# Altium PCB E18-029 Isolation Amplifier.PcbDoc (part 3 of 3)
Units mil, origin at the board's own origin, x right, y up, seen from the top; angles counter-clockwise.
Board outline 5740 x 5970 mil, 4 copper layers (Component Side, V+, V-, Ground), stack 33.234 mil thick; 359 components, 170 nets, 952 pads, 232 vias.
Unrouted connection lines stored in the file: 60.
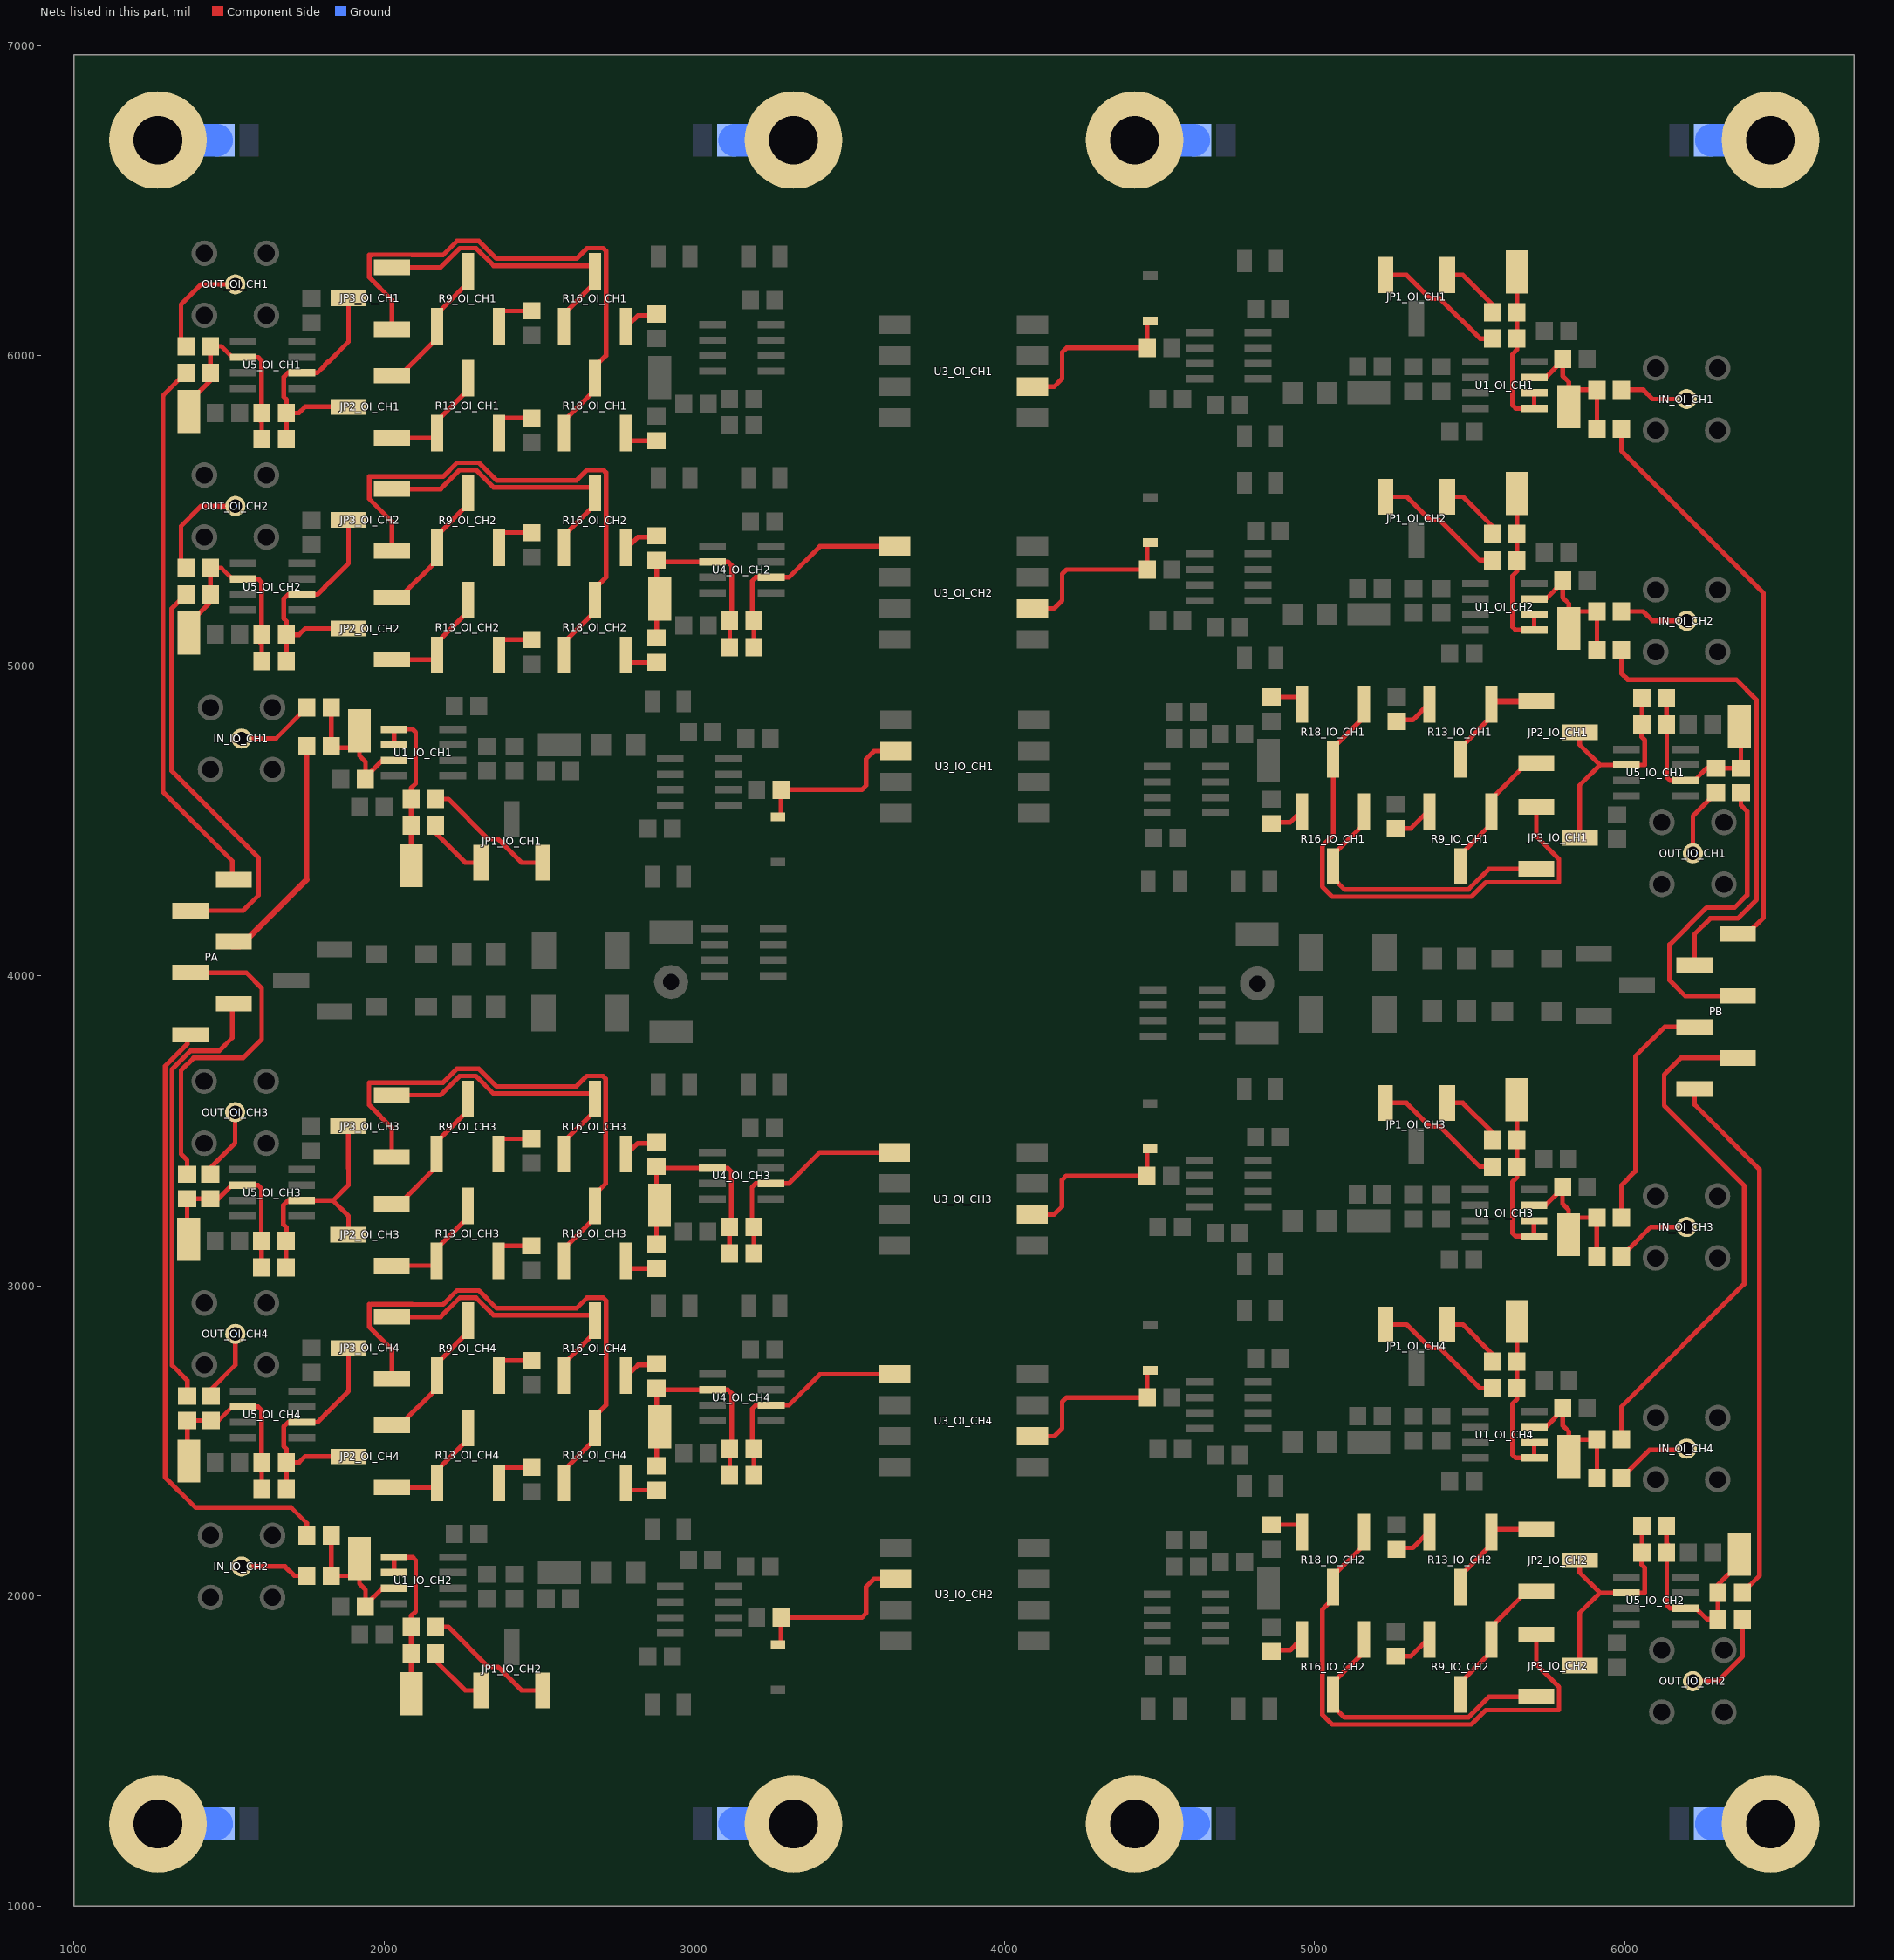
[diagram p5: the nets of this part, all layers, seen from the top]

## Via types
v1: diameter 50, hole 28, Component Side to Ground, tented both sides, 226 vias
v2: diameter 100, hole 50, Component Side to Ground, tented both sides, 6 vias

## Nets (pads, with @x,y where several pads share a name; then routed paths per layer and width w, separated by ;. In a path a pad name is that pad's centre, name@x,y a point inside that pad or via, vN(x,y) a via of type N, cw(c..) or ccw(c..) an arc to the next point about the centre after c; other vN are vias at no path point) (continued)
NetC3_OI_CH2_1: C3_OI_CH2.1 R10_OI_CH2.2 R14_OI_CH2.2 R17_OI_CH2.2 TP4_OI_CH2.1 U4_OI_CH2.6 | length 819.3
  Component Side w15: R17_OI_CH2.2@2878.46,5089.37 2878.46,5205 TP4_OI_CH2.1@2888.46,5215 2878.46,5225 R14_OI_CH2.2@2878.46,5340.63 ; R14_OI_CH2.2@2878.46,5340 2883.46,5335 3103.98,5335 ; U4_OI_CH2.6@3058.98,5335 3108.46,5335 3120.28,5323.18 3120.28,5151.19 R10_OI_CH2.2@3114.09,5145 ; R10_OI_CH2.2@3113.46,5145 3114.09,5144.37 C3_OI_CH2.1@3114.09,5060
NetC3_OI_CH2_2: C3_OI_CH2.2 R10_OI_CH2.1 U3_OI_CH2.5 U4_OI_CH2.2 | length 724.1
  Component Side w15: C3_OI_CH2.2@3192.83,5060 3192.83,5144.37 R10_OI_CH2.1@3193.46,5145 ; R10_OI_CH2.1@3192.83,5145 3186.64,5151.19 3186.64,5273.18 3198.46,5285 U4_OI_CH2.2@3247.95,5285 3305,5285 3405,5385 U3_OI_CH2.5@3646.46,5385 U3_OI_CH2.5@3648.46,5385
NetC3_OI_CH3_1: C3_OI_CH3.1 R10_OI_CH3.2 R14_OI_CH3.2 R17_OI_CH3.2 TP4_OI_CH3.1 U4_OI_CH3.6 | length 819.3
  Component Side w15: R17_OI_CH3.2@2877.83,3134.37 2877.83,3250 TP4_OI_CH3.1@2887.83,3260 2877.83,3270 R14_OI_CH3.2@2877.83,3385.63 ; R14_OI_CH3.2@2877.83,3385 2882.83,3380 3103.35,3380 ; U4_OI_CH3.6@3058.35,3380 3107.83,3380 3119.65,3368.18 3119.65,3196.19 R10_OI_CH3.2@3113.46,3190 ; R10_OI_CH3.2@3112.83,3190 3113.46,3189.37 C3_OI_CH3.1@3113.46,3105
NetC3_OI_CH3_2: C3_OI_CH3.2 R10_OI_CH3.1 U3_OI_CH3.5 U4_OI_CH3.2 | length 724.1
  Component Side w15: C3_OI_CH3.2@3192.2,3105 3192.2,3189.37 R10_OI_CH3.1@3192.83,3190 ; R10_OI_CH3.1@3192.2,3190 3186.01,3196.19 3186.01,3318.18 3197.83,3330 U4_OI_CH3.2@3247.32,3330 3304.37,3330 3404.37,3430 U3_OI_CH3.5@3645.83,3430 U3_OI_CH3.5@3647.83,3430
NetC3_OI_CH4_1: C3_OI_CH4.1 R10_OI_CH4.2 R14_OI_CH4.2 R17_OI_CH4.2 TP4_OI_CH4.1 U4_OI_CH4.6 | length 819.3
  Component Side w15: R17_OI_CH4.2@2878.46,2419.37 2878.46,2535 TP4_OI_CH4.1@2888.46,2545 2878.46,2555 R14_OI_CH4.2@2878.46,2670.63 ; R14_OI_CH4.2@2878.46,2670 2883.46,2665 3103.98,2665 ; U4_OI_CH4.6@3058.98,2665 3108.46,2665 3120.28,2653.18 3120.28,2481.19 R10_OI_CH4.2@3114.09,2475 ; R10_OI_CH4.2@3113.46,2475 3114.09,2474.37 C3_OI_CH4.1@3114.09,2390
NetC3_OI_CH4_2: C3_OI_CH4.2 R10_OI_CH4.1 U3_OI_CH4.5 U4_OI_CH4.2 | length 724.1
  Component Side w15: C3_OI_CH4.2@3192.83,2390 3192.83,2474.37 R10_OI_CH4.1@3193.46,2475 ; R10_OI_CH4.1@3192.83,2475 3186.64,2481.19 3186.64,2603.18 3198.46,2615 U4_OI_CH4.2@3247.95,2615 3305,2615 3405,2715 U3_OI_CH4.5@3646.46,2715 U3_OI_CH4.5@3648.46,2715
NetC4_IO_CH1_1: C4_IO_CH1.1 R12_IO_CH1.1 R15_IO_CH1.2 R21_IO_CH1.2 TP5_IO_CH1.1 U5_IO_CH1.6 | length 679.3
  Component Side w15: C4_IO_CH1.1@6135,4895 6135,4840 R12_IO_CH1.1@6150,4825 ; R12_IO_CH1.1@6135.68,4810 6135.68,4640.68 6146.36,4630 U5_IO_CH1.6@6225,4630 ; U5_IO_CH1.6@6194.49,4630 U5_IO_CH1.6@6225,4630 ; U5_IO_CH1.6@6230,4630 U5_IO_CH1.6@6225,4630 ; R21_IO_CH1.2@6295,4669.37 6374.37,4669.37 R15_IO_CH1.2@6375,4670 ; R21_IO_CH1.2@6295,4670 6265,4670 U5_IO_CH1.6@6225,4630 ; TP5_IO_CH1.1@6370,4805 6375,4800 R15_IO_CH1.2@6375,4670 ; R15_IO_CH1.2@6375,4669.37 R15_IO_CH1.2@6375,4670
NetC4_IO_CH1_2: C4_IO_CH1.2 JP2_IO_CH1.2 JP3_IO_CH1.2 R12_IO_CH1.2 U5_IO_CH1.2 | length 764.3
  Component Side w15: JP3_IO_CH1.2@5855,4445 5855,4615 5920,4680 ; JP2_IO_CH1.2@5855,4785 5855,4745 5920,4680 ; U5_IO_CH1.2@6005.51,4680 6065,4680 6065,4760 6055,4770 R12_IO_CH1.2@6055,4810 ; U5_IO_CH1.2@6010,4680 5920,4680 ; R12_IO_CH1.2@6055.63,4810 6055.63,4890.63 C4_IO_CH1.2@6060,4895
NetC4_IO_CH2_1: C4_IO_CH2.1 R12_IO_CH2.1 R15_IO_CH2.2 R21_IO_CH2.2 TP5_IO_CH2.1 U5_IO_CH2.6 | length 638.7
  Component Side w15: C4_IO_CH2.1@6135,2225 6135,2170 R12_IO_CH2.1@6150,2155 ; R12_IO_CH2.1@6135.68,2140 6135.68,1970.68 6146.36,1960 6230,1960 6265,1925 6300,1925 R21_IO_CH2.2@6300.63,1925.63 ; R15_IO_CH2.2@6300,2010 6300.63,2009.37 R21_IO_CH2.2@6300.63,1925.63 ; R21_IO_CH2.2@6300.63,1925 R21_IO_CH2.2@6300.63,1925.63 ; R15_IO_CH2.2@6300.63,2010 6300.63,2035.63 TP5_IO_CH2.1@6370,2105
NetC4_IO_CH2_2: C4_IO_CH2.2 JP2_IO_CH2.2 JP3_IO_CH2.2 R12_IO_CH2.2 U5_IO_CH2.2 | length 764.3
  Component Side w15: JP3_IO_CH2.2@5855,1775 5855,1945 5920,2010 ; JP2_IO_CH2.2@5855,2115 5855,2075 5920,2010 ; U5_IO_CH2.2@6005.51,2010 6065,2010 6065,2090 6055,2100 R12_IO_CH2.2@6055,2140 ; U5_IO_CH2.2@6010,2010 5920,2010 ; R12_IO_CH2.2@6055.63,2140 6055.63,2220.63 C4_IO_CH2.2@6060,2225
NetC4_OI_CH1_1: C4_OI_CH1.1 R12_OI_CH1.1 R15_OI_CH1.2 R21_OI_CH1.2 TP5_OI_CH1.1 U5_OI_CH1.6 | length 638.7
  Component Side w15: TP5_OI_CH1.1@1370,5850 1439.37,5919.37 R15_OI_CH1.2@1439.37,5945 ; R21_OI_CH1.2@1439.37,6030 R21_OI_CH1.2@1439.37,6029.37 ; R15_OI_CH1.2@1440,5945 1439.37,5945.63 R21_OI_CH1.2@1439.37,6029.37 ; R12_OI_CH1.1@1590,5800 1605,5785 C4_OI_CH1.1@1605,5730 ; R12_OI_CH1.1@1604.32,5815 1604.32,5984.32 1593.64,5995 1510,5995 1475,6030 1440,6030 R21_OI_CH1.2@1439.37,6029.37
NetC4_OI_CH1_2: C4_OI_CH1.2 JP2_OI_CH1.2 JP3_OI_CH1.2 R12_OI_CH1.2 U5_OI_CH1.2 | length 814.3
  Component Side w15: C4_OI_CH1.2@1684.37,5730 R12_OI_CH1.2@1684.37,5815 1684.37,5819.37 R12_OI_CH1.2@1685,5820 ; U5_OI_CH1.2@1734.49,5945 1690,5945 1675.68,5930.68 1675.68,5867.69 1685,5858.37 R12_OI_CH1.2@1685,5820 ; U5_OI_CH1.2@1735,5945 1785,5945 1809.96,5969.96 1809.96,5971.42 1819.04,5980.5 ; 1820,5980 1885,6045 JP3_OI_CH1.2@1885,6185 ; JP2_OI_CH1.2@1885,5835 1745,5835 1725,5815 1685,5815 R12_OI_CH1.2@1685,5820
NetC4_OI_CH2_1: C4_OI_CH2.1 R12_OI_CH2.1 R15_OI_CH2.2 R21_OI_CH2.2 TP5_OI_CH2.1 U5_OI_CH2.6 | length 638.7
  Component Side w15: TP5_OI_CH2.1@1370,5135 1439.37,5204.37 R15_OI_CH2.2@1439.37,5230 ; R21_OI_CH2.2@1439.37,5315 R21_OI_CH2.2@1439.37,5314.37 ; R15_OI_CH2.2@1440,5230 1439.37,5230.63 R21_OI_CH2.2@1439.37,5314.37 ; R12_OI_CH2.1@1590,5085 1605,5070 C4_OI_CH2.1@1605,5015 ; R12_OI_CH2.1@1604.32,5100 1604.32,5269.32 1593.64,5280 1510,5280 1475,5315 1440,5315 R21_OI_CH2.2@1439.37,5314.37
NetC4_OI_CH2_2: C4_OI_CH2.2 JP2_OI_CH2.2 JP3_OI_CH2.2 R12_OI_CH2.2 U5_OI_CH2.2 | length 814.3
  Component Side w15: C4_OI_CH2.2@1684.37,5015 R12_OI_CH2.2@1684.37,5100 1684.37,5104.37 R12_OI_CH2.2@1685,5105 ; U5_OI_CH2.2@1734.49,5230 1690,5230 1675.68,5215.68 1675.68,5152.69 1685,5143.37 R12_OI_CH2.2@1685,5105 ; U5_OI_CH2.2@1735,5230 1785,5230 1809.96,5254.96 1809.96,5256.42 1819.04,5265.5 ; 1820,5265 1885,5330 JP3_OI_CH2.2@1885,5470 ; JP2_OI_CH2.2@1885,5120 1745,5120 1725,5100 1685,5100 R12_OI_CH2.2@1685,5105
NetC4_OI_CH3_1: C4_OI_CH3.1 R12_OI_CH3.1 R15_OI_CH3.2 R21_OI_CH3.2 TP5_OI_CH3.1 U5_OI_CH3.6 | length 681.4
  Component Side w15: R15_OI_CH3.2@1364.37,3280.63 R15_OI_CH3.2@1364.37,3280 ; TP5_OI_CH3.1@1369.37,3145 1364.37,3150 R15_OI_CH3.2@1364.37,3280 ; R21_OI_CH3.2@1439.37,3280 1464.37,3280 U5_OI_CH3.6@1509.37,3325 ; R21_OI_CH3.2@1439.37,3280.63 1365,3280.63 R15_OI_CH3.2@1364.37,3280 ; U5_OI_CH3.6@1544.88,3325 U5_OI_CH3.6@1509.37,3325 ; R12_OI_CH3.1@1589.37,3130 1604.37,3115 C4_OI_CH3.1@1604.37,3060 ; R12_OI_CH3.1@1603.69,3145 1603.69,3314.32 1593.01,3325 U5_OI_CH3.6@1509.37,3325
NetC4_OI_CH3_2: C4_OI_CH3.2 JP2_OI_CH3.2 JP3_OI_CH3.2 R12_OI_CH3.2 U5_OI_CH3.2 | length 769.3
  Component Side w15: C4_OI_CH3.2@1683.74,3060 R12_OI_CH3.2@1683.74,3145 1683.74,3149.37 R12_OI_CH3.2@1684.37,3150 ; R12_OI_CH3.2@1684.37,3145 R12_OI_CH3.2@1684.37,3150 ; U5_OI_CH3.2@1733.86,3275 1689.37,3275 1675.05,3260.68 1675.05,3197.69 1684.37,3188.37 R12_OI_CH3.2@1684.37,3150 ; U5_OI_CH3.2@1734.37,3275 1835,3275 ; 1884.37,3379.37 JP3_OI_CH3.2@1884.37,3515 ; 1885,3380 1885,3325 1835,3275 ; JP2_OI_CH3.2@1890,3165 1885,3170 1885,3225 1835,3275
NetC4_OI_CH4_1: C4_OI_CH4.1 R12_OI_CH4.1 R15_OI_CH4.2 R21_OI_CH4.2 TP5_OI_CH4.1 U5_OI_CH4.6 | length 681.4
  Component Side w15: R15_OI_CH4.2@1365,2565.63 R15_OI_CH4.2@1365,2565 ; TP5_OI_CH4.1@1370,2430 1365,2435 R15_OI_CH4.2@1365,2565 ; R21_OI_CH4.2@1440,2565 1465,2565 U5_OI_CH4.6@1510,2610 ; R21_OI_CH4.2@1440,2565.63 1365.63,2565.63 R15_OI_CH4.2@1365,2565 ; U5_OI_CH4.6@1545.51,2610 U5_OI_CH4.6@1510,2610 ; R12_OI_CH4.1@1590,2415 1605,2400 C4_OI_CH4.1@1605,2345 ; R12_OI_CH4.1@1604.32,2430 1604.32,2599.32 1593.64,2610 U5_OI_CH4.6@1510,2610
NetC4_OI_CH4_2: C4_OI_CH4.2 JP2_OI_CH4.2 JP3_OI_CH4.2 R12_OI_CH4.2 U5_OI_CH4.2 | length 814.3
  Component Side w15: C4_OI_CH4.2@1684.37,2345 R12_OI_CH4.2@1684.37,2430 1684.37,2434.37 R12_OI_CH4.2@1685,2435 ; U5_OI_CH4.2@1734.49,2560 1690,2560 1675.68,2545.68 1675.68,2482.69 1685,2473.37 R12_OI_CH4.2@1685,2435 ; U5_OI_CH4.2@1735,2560 1785,2560 1809.96,2584.96 1809.96,2586.42 1819.04,2595.5 ; 1820,2595 1885,2660 JP3_OI_CH4.2@1885,2800 ; JP2_OI_CH4.2@1885,2450 1745,2450 1725,2430 1685,2430 R12_OI_CH4.2@1685,2435
NetD1_IO_CH1_2: D1_IO_CH1.2 R5_IO_CH1.2 U3_IO_CH1.2 | length 591.9
  Component Side w15: R5_IO_CH1.2@3265,4600 R5_IO_CH1.2@3279.37,4614.37 ; R5_IO_CH1.2@3275,4600 R5_IO_CH1.2@3279.37,4600 ; D1_IO_CH1.2@3279.37,4524.37 R5_IO_CH1.2@3279.37,4600 ; U3_IO_CH1.2@3630,4725 U3_IO_CH1.2@3649.54,4725 3579.53,4725 3553.87,4699.34 3553.87,4613.87 3540,4600 R5_IO_CH1.2@3279.37,4600
NetD1_IO_CH2_2: D1_IO_CH2.2 R5_IO_CH2.2 U3_IO_CH2.2 | length 591.9
  Component Side w15: R5_IO_CH2.2@3265,1930 R5_IO_CH2.2@3279.37,1944.37 ; R5_IO_CH2.2@3275,1930 R5_IO_CH2.2@3279.37,1930 ; D1_IO_CH2.2@3279.37,1854.37 R5_IO_CH2.2@3279.37,1930 ; U3_IO_CH2.2@3630,2055 U3_IO_CH2.2@3649.54,2055 3579.53,2055 3553.87,2029.34 3553.87,1943.87 3540,1930 R5_IO_CH2.2@3279.37,1930
NetD1_OI_CH1_2: D1_OI_CH1.2 R5_OI_CH1.2 U3_OI_CH1.2 | length 572.3
  Component Side w15: U3_OI_CH1.2@4090.46,5900 4160.47,5900 4186.13,5925.66 4186.13,6011.13 4200,6025 R5_OI_CH1.2@4460.63,6025 ; R5_OI_CH1.2@4460.63,6010.63 R5_OI_CH1.2@4475,6025 ; D1_OI_CH1.2@4460.63,6100.63 R5_OI_CH1.2@4460.63,6025 ; R5_OI_CH1.2@4465,6025 R5_OI_CH1.2@4460.63,6025
NetD1_OI_CH2_2: D1_OI_CH2.2 R5_OI_CH2.2 U3_OI_CH2.2 | length 572.3
  Component Side w15: U3_OI_CH2.2@4090.46,5185 4160.47,5185 4186.13,5210.66 4186.13,5296.13 4200,5310 R5_OI_CH2.2@4460.63,5310 ; R5_OI_CH2.2@4460.63,5295.63 R5_OI_CH2.2@4475,5310 ; D1_OI_CH2.2@4460.63,5385.63 R5_OI_CH2.2@4460.63,5310 ; R5_OI_CH2.2@4465,5310 R5_OI_CH2.2@4460.63,5310
NetD1_OI_CH3_2: D1_OI_CH3.2 R5_OI_CH3.2 U3_OI_CH3.2 | length 572.3
  Component Side w15: U3_OI_CH3.2@4089.83,3230 4159.84,3230 4185.5,3255.66 4185.5,3341.13 4199.37,3355 R5_OI_CH3.2@4460,3355 ; R5_OI_CH3.2@4460,3340.63 R5_OI_CH3.2@4474.37,3355 ; D1_OI_CH3.2@4460,3430.63 R5_OI_CH3.2@4460,3355 ; R5_OI_CH3.2@4464.37,3355 R5_OI_CH3.2@4460,3355
NetD1_OI_CH4_2: D1_OI_CH4.2 R5_OI_CH4.2 U3_OI_CH4.2 | length 572.3
  Component Side w15: U3_OI_CH4.2@4090.46,2515 4160.47,2515 4186.13,2540.66 4186.13,2626.13 4200,2640 R5_OI_CH4.2@4460.63,2640 ; R5_OI_CH4.2@4460.63,2625.63 R5_OI_CH4.2@4475,2640 ; D1_OI_CH4.2@4460.63,2715.63 R5_OI_CH4.2@4460.63,2640 ; R5_OI_CH4.2@4465,2640 R5_OI_CH4.2@4460.63,2640
NetIN_IO_CH1_1: IN_IO_CH1.1 R20_IO_CH1.2 | length 252.1
  Component Side w15: IN_IO_CH1.1@1540,4765 1650.63,4765 R20_IO_CH1.2@1750.63,4865
NetIN_IO_CH2_1: IN_IO_CH2.1 R20_IO_CH2.2 | length 223.1
  Component Side w15: IN_IO_CH2.1@1540,2095 1680,2095 1710,2065 R20_IO_CH2.2@1750.63,2065
NetIN_OI_CH1_1: IN_OI_CH1.1 R20_OI_CH1.2 | length 223.1
  Component Side w15: R20_OI_CH1.2@5989.37,5890 6060,5890 6090,5860 IN_OI_CH1.1@6200,5860
NetIN_OI_CH2_1: IN_OI_CH2.1 R20_OI_CH2.2 | length 223.1
  Component Side w15: R20_OI_CH2.2@5989.37,5175 6060,5175 6090,5145 IN_OI_CH2.1@6200,5145
NetIN_OI_CH3_1: IN_OI_CH3.1 R20_OI_CH3.2 | length 250
  Component Side w15: R20_OI_CH3.2@5989.37,3095 6084.37,3190 IN_OI_CH3.1@6199.37,3190 IN_OI_CH3.1@6200,3190
NetIN_OI_CH4_1: IN_OI_CH4.1 R20_OI_CH4.2 | length 250
  Component Side w15: R20_OI_CH4.2@5989.37,2380 6080,2470.63 6195.63,2470.63 IN_OI_CH4.1@6200,2475
NetJP1_IO_CH1_1: JP1_IO_CH1.1 R3_IO_CH1.1 | length 429.9
  Component Side w15: R3_IO_CH1.1@2166.54,4570 2206.54,4570 2335.54,4441 2367.08,4441 2443.08,4365 JP1_IO_CH1.1@2511.54,4365
NetJP1_IO_CH1_3: JP1_IO_CH1.3 R6_IO_CH1.1 | length 209.4
  Component Side w15: R6_IO_CH1.1@2166.54,4485 2166.54,4460 2261.54,4365 JP1_IO_CH1.3@2311.54,4365
NetJP1_IO_CH2_1: JP1_IO_CH2.1 R3_IO_CH2.1 | length 429.9
  Component Side w15: R3_IO_CH2.1@2166.54,1900 2206.54,1900 2335.54,1771 2367.08,1771 2443.08,1695 JP1_IO_CH2.1@2511.54,1695
NetJP1_IO_CH2_3: JP1_IO_CH2.3 R6_IO_CH2.1 | length 209.4
  Component Side w15: R6_IO_CH2.1@2166.54,1815 2166.54,1790 2261.54,1695 JP1_IO_CH2.3@2311.54,1695
NetJP1_OI_CH1_1: JP1_OI_CH1.1 R3_OI_CH1.1 | length 429.9
  Component Side w15: JP1_OI_CH1.1@5228.46,6260 5296.92,6260 5372.92,6184 5404.46,6184 5533.46,6055 R3_OI_CH1.1@5573.46,6055
NetJP1_OI_CH1_3: JP1_OI_CH1.3 R6_OI_CH1.1 | length 209.4
  Component Side w15: JP1_OI_CH1.3@5428.46,6260 5478.46,6260 5573.46,6165 R6_OI_CH1.1@5573.46,6140
NetJP1_OI_CH2_1: JP1_OI_CH2.1 R3_OI_CH2.1 | length 429.9
  Component Side w15: JP1_OI_CH2.1@5228.46,5545 5296.92,5545 5372.92,5469 5404.46,5469 5533.46,5340 R3_OI_CH2.1@5573.46,5340
NetJP1_OI_CH2_3: JP1_OI_CH2.3 R6_OI_CH2.1 | length 209.4
  Component Side w15: JP1_OI_CH2.3@5428.46,5545 5478.46,5545 5573.46,5450 R6_OI_CH2.1@5573.46,5425
NetJP1_OI_CH3_1: JP1_OI_CH3.1 R3_OI_CH3.1 | length 429.9
  Component Side w15: JP1_OI_CH3.1@5227.83,3590 5296.29,3590 5372.29,3514 5403.83,3514 5532.83,3385 R3_OI_CH3.1@5572.83,3385
NetJP1_OI_CH3_3: JP1_OI_CH3.3 R6_OI_CH3.1 | length 209.4
  Component Side w15: JP1_OI_CH3.3@5427.83,3590 5477.83,3590 5572.83,3495 R6_OI_CH3.1@5572.83,3470
NetJP1_OI_CH4_1: JP1_OI_CH4.1 R3_OI_CH4.1 | length 429.9
  Component Side w15: JP1_OI_CH4.1@5228.46,2875 5296.92,2875 5372.92,2799 5404.46,2799 5533.46,2670 R3_OI_CH4.1@5573.46,2670
NetJP1_OI_CH4_3: JP1_OI_CH4.3 R6_OI_CH4.1 | length 209.4
  Component Side w15: JP1_OI_CH4.3@5428.46,2875 5478.46,2875 5573.46,2780 R6_OI_CH4.1@5573.46,2755
NetJP2_IO_CH1_1: JP2_IO_CH1.1 R9_IO_CH1.1 R9_IO_CH1.2 | length 378.3
  Component Side w15: R9_IO_CH1.2@5470,4352.83 5470,4390 R9_IO_CH1.1@5575,4495 ; R9_IO_CH1.1@5570,4570 5685,4685 JP2_IO_CH1.1@5715,4685
NetJP2_IO_CH1_3: JP2_IO_CH1.3 R13_IO_CH1.1 R13_IO_CH1.2 | length 332.7
  Component Side w15: R13_IO_CH1.2@5470,4697.83 5470,4735 R13_IO_CH1.1@5575,4840
  Component Side w20: R13_IO_CH1.1@5570,4880 5575,4885 JP2_IO_CH1.3@5715,4885
NetJP2_IO_CH2_1: JP2_IO_CH2.1 R9_IO_CH2.1 R9_IO_CH2.2 | length 378.3
  Component Side w15: R9_IO_CH2.2@5470,1682.83 5470,1720 R9_IO_CH2.1@5575,1825 ; R9_IO_CH2.1@5570,1900 5685,2015 JP2_IO_CH2.1@5715,2015
NetJP2_IO_CH2_3: JP2_IO_CH2.3 R13_IO_CH2.1 R13_IO_CH2.2 | length 332.7
  Component Side w15: R13_IO_CH2.2@5470,2027.83 5470,2065 R13_IO_CH2.1@5575,2170 ; R13_IO_CH2.1@5570,2210 5575,2215 JP2_IO_CH2.3@5715,2215
NetJP2_OI_CH1_1: JP2_OI_CH1.1 R9_OI_CH1.1 R9_OI_CH1.2 | length 383.2
  Component Side w15: JP2_OI_CH1.1@2025,5935 2050,5935 R9_OI_CH1.1@2170,6055 ; R9_OI_CH1.1@2170,6095 2170,6135 R9_OI_CH1.2@2275,6240
NetJP2_OI_CH1_3: JP2_OI_CH1.3 R13_OI_CH1.1 R13_OI_CH1.2 | length 326.4
  Component Side w15: JP2_OI_CH1.3@2025,5735 R13_OI_CH1.1@2170,5735 ; R13_OI_CH1.1@2170,5750 2170,5790 R13_OI_CH1.2@2270,5890
NetJP2_OI_CH2_1: JP2_OI_CH2.1 R9_OI_CH2.1 R9_OI_CH2.2 | length 383.2
  Component Side w15: JP2_OI_CH2.1@2025,5220 2050,5220 R9_OI_CH2.1@2170,5340 ; R9_OI_CH2.1@2170,5380 2170,5420 R9_OI_CH2.2@2275,5525
NetJP2_OI_CH2_3: JP2_OI_CH2.3 R13_OI_CH2.1 R13_OI_CH2.2 | length 326.4
  Component Side w15: JP2_OI_CH2.3@2025,5020 R13_OI_CH2.1@2170,5020 ; R13_OI_CH2.1@2170,5035 2170,5075 R13_OI_CH2.2@2270,5175
NetJP2_OI_CH3_1: JP2_OI_CH3.1 R9_OI_CH3.1 R9_OI_CH3.2 | length 383.2
  Component Side w15: JP2_OI_CH3.1@2024.37,3265 2049.37,3265 R9_OI_CH3.1@2169.37,3385 ; R9_OI_CH3.1@2169.37,3425 2169.37,3465 R9_OI_CH3.2@2274.37,3570
NetJP2_OI_CH3_3: JP2_OI_CH3.3 R13_OI_CH3.1 R13_OI_CH3.2 | length 326.4
  Component Side w15: JP2_OI_CH3.3@2024.37,3065 R13_OI_CH3.1@2169.37,3065 ; R13_OI_CH3.1@2169.37,3080 2169.37,3120 R13_OI_CH3.2@2269.37,3220
NetJP2_OI_CH4_1: JP2_OI_CH4.1 R9_OI_CH4.1 R9_OI_CH4.2 | length 383.2
  Component Side w15: JP2_OI_CH4.1@2025,2550 2050,2550 R9_OI_CH4.1@2170,2670 ; R9_OI_CH4.1@2170,2710 2170,2750 R9_OI_CH4.2@2275,2855
NetJP2_OI_CH4_3: JP2_OI_CH4.3 R13_OI_CH4.1 R13_OI_CH4.2 | length 326.4
  Component Side w15: JP2_OI_CH4.3@2025,2350 R13_OI_CH4.1@2170,2350 ; R13_OI_CH4.1@2170,2365 2170,2405 R13_OI_CH4.2@2270,2505
NetJP3_IO_CH1_1: JP3_IO_CH1.1 R16_IO_CH1.1 R16_IO_CH1.2 | length 883.5
  Component Side w15: R16_IO_CH1.2@5060,4315 5096.72,4278.28 5496.11,4278.28 5562.83,4345 JP3_IO_CH1.1@5715,4345 ; R16_IO_CH1.2@5060,4352.83 5060,4390 R16_IO_CH1.1@5165,4495
NetJP3_IO_CH1_3: JP3_IO_CH1.3 R18_IO_CH1.1 R18_IO_CH1.2 | length 1586.6
  Component Side w15: R18_IO_CH1.2@5060,4655 5060,4453.5 5024.81,4418.31 5024.81,4287.36 5056.89,4255.28 5505.63,4255.28 5551.85,4301.5 5788.5,4301.5 5788.5,4376.42 5715,4449.92 JP3_IO_CH1.3@5715,4545 ; R18_IO_CH1.2@5060,4735 R18_IO_CH1.1@5155,4830
NetJP3_IO_CH2_1: JP3_IO_CH2.1 R16_IO_CH2.1 R16_IO_CH2.2 | length 883.5
  Component Side w15: R16_IO_CH2.2@5060,1645 5096.72,1608.28 5496.11,1608.28 5562.83,1675 JP3_IO_CH2.1@5715,1675 ; R16_IO_CH2.2@5060,1682.83 5060,1720 R16_IO_CH2.1@5165,1825
NetJP3_IO_CH2_3: JP3_IO_CH2.3 R18_IO_CH2.1 R18_IO_CH2.2 | length 1628.8
  Component Side w15: R18_IO_CH2.2@5060,1990 5024.81,1954.81 5024.81,1617.36 5056.89,1585.28 5505.63,1585.28 5551.85,1631.5 5788.5,1631.5 5788.5,1706.42 5715,1779.92 JP3_IO_CH2.3@5715,1875 ; R18_IO_CH2.2@5060,2027.83 5060,2065 R18_IO_CH2.1@5155,2160
NetJP3_OI_CH1_1: JP3_OI_CH1.1 R16_OI_CH1.1 R16_OI_CH1.2 | length 896.8
  Component Side w15: JP3_OI_CH1.1@2025,6285 2182.17,6285 2243.89,6346.72 2296.11,6346.72 2352.83,6290 2670,6290 2685,6305 R16_OI_CH1.2@2685,6295 ; R16_OI_CH1.1@2585,6140 2680,6235 R16_OI_CH1.2@2680,6272.17
NetJP3_OI_CH1_3: JP3_OI_CH1.3 R18_OI_CH1.1 R18_OI_CH1.2 | length 1660.8
  Component Side w15: JP3_OI_CH1.3@2025,6085 2025,6180.08 1951.5,6253.58 1951.5,6325.5 1952,6325 1960.08,6325 1960.58,6325.5 2089.42,6325.5 2089.92,6325 2189.65,6325 2234.37,6369.72 2305.63,6369.72 2362.35,6313 2620.17,6313 2653.89,6346.72 2706.11,6346.72 2715.19,6337.64 2715.19,6000.19 R18_OI_CH1.2@2680,5965 ; R18_OI_CH1.1@2580,5790 2680,5890 R18_OI_CH1.2@2680,5927.17
NetJP3_OI_CH2_1: JP3_OI_CH2.1 R16_OI_CH2.1 R16_OI_CH2.2 | length 896.8
  Component Side w15: JP3_OI_CH2.1@2025,5570 2182.17,5570 2243.89,5631.72 2296.11,5631.72 2352.83,5575 2670,5575 2685,5590 R16_OI_CH2.2@2685,5580 ; R16_OI_CH2.1@2585,5425 2680,5520 R16_OI_CH2.2@2680,5557.17
NetJP3_OI_CH2_3: JP3_OI_CH2.3 R18_OI_CH2.1 R18_OI_CH2.2 | length 1660.8
  Component Side w15: JP3_OI_CH2.3@2025,5370 2025,5465.08 1951.5,5538.58 1951.5,5610.5 1952,5610 1960.08,5610 1960.58,5610.5 2089.42,5610.5 2089.92,5610 2189.65,5610 2234.37,5654.72 2305.63,5654.72 2362.35,5598 2620.17,5598 2653.89,5631.72 2706.11,5631.72 2715.19,5622.64 2715.19,5285.19 R18_OI_CH2.2@2680,5250 ; R18_OI_CH2.1@2580,5075 2680,5175 R18_OI_CH2.2@2680,5212.17
NetJP3_OI_CH3_1: JP3_OI_CH3.1 R16_OI_CH3.1 R16_OI_CH3.2 | length 896.8
  Component Side w15: JP3_OI_CH3.1@2024.37,3615 2181.54,3615 2243.26,3676.72 2295.48,3676.72 2352.2,3620 2669.37,3620 2684.37,3635 R16_OI_CH3.2@2684.37,3625 ; R16_OI_CH3.1@2584.37,3470 2679.37,3565 R16_OI_CH3.2@2679.37,3602.17
NetJP3_OI_CH3_3: JP3_OI_CH3.3 R18_OI_CH3.1 R18_OI_CH3.2 | length 1660.8
  Component Side w15: JP3_OI_CH3.3@2024.37,3415 2024.37,3510.08 1950.87,3583.58 1950.87,3655.5 1951.37,3655 1959.45,3655 1959.95,3655.5 2088.79,3655.5 2089.29,3655 2189.02,3655 2233.74,3699.72 2305,3699.72 2361.72,3643 2619.54,3643 2653.26,3676.72 2705.48,3676.72 2714.56,3667.64 2714.56,3330.19 R18_OI_CH3.2@2679.37,3295 ; R18_OI_CH3.1@2579.37,3120 2679.37,3220 R18_OI_CH3.2@2679.37,3257.17
NetJP3_OI_CH4_1: JP3_OI_CH4.1 R16_OI_CH4.1 R16_OI_CH4.2 | length 896.8
  Component Side w15: JP3_OI_CH4.1@2025,2900 2182.17,2900 2243.89,2961.72 2296.11,2961.72 2352.83,2905 2670,2905 2685,2920 R16_OI_CH4.2@2685,2910 ; R16_OI_CH4.1@2585,2755 2680,2850 R16_OI_CH4.2@2680,2887.17
NetJP3_OI_CH4_3: JP3_OI_CH4.3 R18_OI_CH4.1 R18_OI_CH4.2 | length 1660.8
  Component Side w15: JP3_OI_CH4.3@2025,2700 2025,2795.08 1951.5,2868.58 1951.5,2940.5 1952,2940 1960.08,2940 1960.58,2940.5 2089.42,2940.5 2089.92,2940 2189.65,2940 2234.37,2984.72 2305.63,2984.72 2362.35,2928 2620.17,2928 2653.89,2961.72 2706.11,2961.72 2715.19,2952.64 2715.19,2615.19 R18_OI_CH4.2@2680,2580 ; R18_OI_CH4.1@2580,2405 2680,2505 R18_OI_CH4.2@2680,2542.17
NetJPA1_1: JPA1.1 MA1.1 | length 190
  Ground w105: MA1.1@1270,6695 JPA1.1@1460,6695
NetJPA2_1: JPA2.1 MA2.1 | length 195
  Ground w105: JPA2.1@3130,6695 MA2.1@3320,6695 MA2.1@3325,6695
NetJPA3_1: JPA3.1 MA3.1 | length 195
  Ground w105: MA3.1@1265,1265 MA3.1@1270,1265 JPA3.1@1460,1265
NetJPA4_1: JPA4.1 MA4.1 | length 190
  Ground w105: JPA4.1@3130,1265 MA4.1@3320,1265
NetJPB1_1: JPB1.1 MB1.1 | length 195
  Ground w105: MB1.1@4415,6695 MB1.1@4420,6695 JPB1.1@4610,6695
NetJPB2_1: JPB2.1 MB2.1 | length 190
  Ground w105: JPB2.1@6280,6695 MB2.1@6470,6695
NetJPB3_1: JPB3.1 MB3.1 | length 190
  Ground w105: MB3.1@4420,1265 JPB3.1@4610,1265
NetJPB4_1: JPB4.1 MB4.1 | length 190
  Ground w105: JPB4.1@6280,1265 MB4.1@6470,1265
NetOUT_IO_CH1_1: OUT_IO_CH1.1 R21_IO_CH1.1 | length 226.7
  Component Side w15: OUT_IO_CH1.1@6220,4395 6220,4515 6295,4590 R21_IO_CH1.1@6295,4590.63
NetOUT_IO_CH2_1: OUT_IO_CH2.1 R21_IO_CH2.1 | length 313.6
  Component Side w15: OUT_IO_CH2.1@6220,1725 6300.38,1725 6380,1804.62 6380,1924.37 R21_IO_CH2.1@6379.37,1925
NetOUT_OI_CH1_1: OUT_OI_CH1.1 R21_OI_CH1.1 | length 343.4
  Component Side w15: R21_OI_CH1.1@1360.63,6030 1345,6045.63 1345,6165 1410,6230 OUT_OI_CH1.1@1520,6230
NetOUT_OI_CH2_1: OUT_OI_CH2.1 R21_OI_CH2.1 | length 343.4
  Component Side w15: R21_OI_CH2.1@1360.63,5315 1345,5330.63 1345,5450 1410,5515 OUT_OI_CH2.1@1520,5515
NetOUT_OI_CH3_1: OUT_OI_CH3.1 R21_OI_CH3.1 | length 233.8
  Component Side w15: R21_OI_CH3.1@1439.37,3359.37 1439.37,3380 1519.37,3460 OUT_OI_CH3.1@1519.37,3560
NetOUT_OI_CH4_1: OUT_OI_CH4.1 R21_OI_CH4.1 | length 233.8
  Component Side w15: R21_OI_CH4.1@1440,2644.37 1440,2665 1520,2745 OUT_OI_CH4.1@1520,2845
NetR3_IO_CH1_2: R3_IO_CH1.2 R6_IO_CH1.2 TP2_IO_CH1.1 U1_IO_CH1.1 U1_IO_CH1.2 | length 570.1
  Component Side w15: U1_IO_CH1.2@2031.54,4745 2032.05,4745.51 U1_IO_CH1.1@2032.05,4795 2091.54,4795 2101.54,4785 2101.54,4620 2086.54,4605 R3_IO_CH1.2@2086.54,4570 ; TP2_IO_CH1.1@2085,4355 2087.17,4357.17 R6_IO_CH1.2@2087.17,4485 ; R6_IO_CH1.2@2086.54,4485 2087.17,4485.63 R3_IO_CH1.2@2087.17,4570 ; R3_IO_CH1.2@2093.36,4570 2091.54,4570 R3_IO_CH1.2@2096.54,4565
NetR3_IO_CH2_2: R3_IO_CH2.2 R6_IO_CH2.2 TP2_IO_CH2.1 U1_IO_CH2.1 U1_IO_CH2.2 | length 570.1
  Component Side w15: U1_IO_CH2.2@2031.54,2075 2032.05,2075.51 U1_IO_CH2.1@2032.05,2125 2091.54,2125 2101.54,2115 2101.54,1950 2086.54,1935 R3_IO_CH2.2@2086.54,1900 ; TP2_IO_CH2.1@2085,1685 2087.17,1687.17 R6_IO_CH2.2@2087.17,1815 ; R6_IO_CH2.2@2086.54,1815 2087.17,1815.63 R3_IO_CH2.2@2087.17,1900 ; R3_IO_CH2.2@2093.36,1900 2091.54,1900 R3_IO_CH2.2@2096.54,1895
NetR3_OI_CH1_2: R3_OI_CH1.2 R6_OI_CH1.2 TP2_OI_CH1.1 U1_OI_CH1.1 U1_OI_CH1.2 | length 570.1
  Component Side w15: R3_OI_CH1.2@5643.46,6060 5648.46,6055 R3_OI_CH1.2@5646.64,6055 ; R3_OI_CH1.2@5652.83,6055 5652.83,6139.37 R6_OI_CH1.2@5653.46,6140 ; R6_OI_CH1.2@5652.83,6140 5652.83,6267.83 TP2_OI_CH1.1@5655,6270 ; R3_OI_CH1.2@5653.46,6055 5653.46,6020 5638.46,6005 5638.46,5840 5648.46,5830 U1_OI_CH1.1@5707.95,5830 5707.95,5879.49 U1_OI_CH1.2@5708.46,5880
NetR3_OI_CH2_2: R3_OI_CH2.2 R6_OI_CH2.2 TP2_OI_CH2.1 U1_OI_CH2.1 U1_OI_CH2.2 | length 570.1
  Component Side w15: R3_OI_CH2.2@5643.46,5345 5648.46,5340 R3_OI_CH2.2@5646.64,5340 ; R3_OI_CH2.2@5652.83,5340 5652.83,5424.37 R6_OI_CH2.2@5653.46,5425 ; R6_OI_CH2.2@5652.83,5425 5652.83,5552.83 TP2_OI_CH2.1@5655,5555 ; R3_OI_CH2.2@5653.46,5340 5653.46,5305 5638.46,5290 5638.46,5125 5648.46,5115 U1_OI_CH2.1@5707.95,5115 5707.95,5164.49 U1_OI_CH2.2@5708.46,5165
NetR3_OI_CH3_2: R3_OI_CH3.2 R6_OI_CH3.2 TP2_OI_CH3.1 U1_OI_CH3.1 U1_OI_CH3.2 | length 570.1
  Component Side w15: R3_OI_CH3.2@5642.83,3390 5647.83,3385 R3_OI_CH3.2@5646.01,3385 ; R3_OI_CH3.2@5652.2,3385 5652.2,3469.37 R6_OI_CH3.2@5652.83,3470 ; R6_OI_CH3.2@5652.2,3470 5652.2,3597.83 TP2_OI_CH3.1@5654.37,3600 ; R3_OI_CH3.2@5652.83,3385 5652.83,3350 5637.83,3335 5637.83,3170 5647.83,3160 U1_OI_CH3.1@5707.32,3160 5707.32,3209.49 U1_OI_CH3.2@5707.83,3210
NetR3_OI_CH4_2: R3_OI_CH4.2 R6_OI_CH4.2 TP2_OI_CH4.1 U1_OI_CH4.1 U1_OI_CH4.2 | length 570.1
  Component Side w15: R3_OI_CH4.2@5643.46,2675 5648.46,2670 R3_OI_CH4.2@5646.64,2670 ; R3_OI_CH4.2@5652.83,2670 5652.83,2754.37 R6_OI_CH4.2@5653.46,2755 ; R6_OI_CH4.2@5652.83,2755 5652.83,2882.83 TP2_OI_CH4.1@5655,2885 ; R3_OI_CH4.2@5653.46,2670 5653.46,2635 5638.46,2620 5638.46,2455 5648.46,2445 U1_OI_CH4.1@5707.95,2445 5707.95,2494.49 U1_OI_CH4.2@5708.46,2495
NetR7_IO_CH1_2: R7_IO_CH1.2 R19_IO_CH1.1 R20_IO_CH1.1 TP1_IO_CH1.1 U1_IO_CH1.3 | length 492.6
  Component Side w15: R19_IO_CH1.1@1829.37,4735 R19_IO_CH1.1@1830,4735 ; R20_IO_CH1.1@1829.37,4865 1829.37,4735.63 R19_IO_CH1.1@1830,4735 ; TP1_IO_CH1.1@1920,4790 TP1_IO_CH1.1@1920,4735 ; R7_IO_CH1.2@1939.37,4640 R7_IO_CH1.2@1940,4640.63 ; R7_IO_CH1.2@1940,4640 R7_IO_CH1.2@1940,4640.63 ; U1_IO_CH1.3@2030,4695 1994.37,4695 R7_IO_CH1.2@1940,4640.63 ; R19_IO_CH1.1@1830,4735 TP1_IO_CH1.1@1920,4735 ; TP1_IO_CH1.1@1920,4735 1920,4710 1940,4690 R7_IO_CH1.2@1940,4640.63
NetR7_IO_CH2_2: R7_IO_CH2.2 R19_IO_CH2.1 R20_IO_CH2.1 TP1_IO_CH2.1 U1_IO_CH2.3 | length 492.6
  Component Side w15: R20_IO_CH2.1@1829.37,2065 R20_IO_CH2.1@1830,2065 ; R19_IO_CH2.1@1829.37,2195 1829.37,2065.63 R20_IO_CH2.1@1830,2065 ; TP1_IO_CH2.1@1920,2120 TP1_IO_CH2.1@1920,2065 ; R7_IO_CH2.2@1939.37,1970 R7_IO_CH2.2@1940,1970.63 ; R7_IO_CH2.2@1940,1970 R7_IO_CH2.2@1940,1970.63 ; U1_IO_CH2.3@2030,2025 1994.37,2025 R7_IO_CH2.2@1940,1970.63 ; R20_IO_CH2.1@1830,2065 TP1_IO_CH2.1@1920,2065 ; TP1_IO_CH2.1@1920,2065 1920,2040 1940,2020 R7_IO_CH2.2@1940,1970.63
NetR7_OI_CH1_2: R7_OI_CH1.2 R19_OI_CH1.1 R20_OI_CH1.1 TP1_OI_CH1.1 U1_OI_CH1.3 | length 488.5
  Component Side w15: U1_OI_CH1.3@5710,5930 5745.63,5930 R7_OI_CH1.2@5800,5984.37 ; R7_OI_CH1.2@5800,5985 R7_OI_CH1.2@5800,5984.37 ; R7_OI_CH1.2@5800.63,5985 R7_OI_CH1.2@5800,5984.37 ; TP1_OI_CH1.1@5820,5835 TP1_OI_CH1.1@5820,5890 ; R19_OI_CH1.1@5910,5765 5910.63,5765.63 R20_OI_CH1.1@5910.63,5889.37 ; R7_OI_CH1.2@5800,5984.37 5800,5935 5820,5915 TP1_OI_CH1.1@5820,5890 ; TP1_OI_CH1.1@5820,5890 R20_OI_CH1.1@5910,5890 ; R20_OI_CH1.1@5910,5890 R20_OI_CH1.1@5910.63,5889.37 ; R20_OI_CH1.1@5910,5890 R20_OI_CH1.1@5910.63,5890 R20_OI_CH1.1@5910.63,5889.37
NetR7_OI_CH2_2: R7_OI_CH2.2 R19_OI_CH2.1 R20_OI_CH2.1 TP1_OI_CH2.1 U1_OI_CH2.3 | length 488.5
  Component Side w15: U1_OI_CH2.3@5710,5215 5745.63,5215 R7_OI_CH2.2@5800,5269.37 ; R7_OI_CH2.2@5800,5270 R7_OI_CH2.2@5800,5269.37 ; R7_OI_CH2.2@5800.63,5270 R7_OI_CH2.2@5800,5269.37 ; TP1_OI_CH2.1@5820,5120 TP1_OI_CH2.1@5820,5175 ; R19_OI_CH2.1@5910,5050 5910.63,5050.63 R20_OI_CH2.1@5910.63,5174.37 ; R7_OI_CH2.2@5800,5269.37 5800,5220 5820,5200 TP1_OI_CH2.1@5820,5175 ; TP1_OI_CH2.1@5820,5175 R20_OI_CH2.1@5910,5175 ; R20_OI_CH2.1@5910,5175 R20_OI_CH2.1@5910.63,5174.37 ; R20_OI_CH2.1@5910,5175 R20_OI_CH2.1@5910.63,5175 R20_OI_CH2.1@5910.63,5174.37
NetR7_OI_CH3_2: R7_OI_CH3.2 R19_OI_CH3.1 R20_OI_CH3.1 TP1_OI_CH3.1 U1_OI_CH3.3 | length 488.5
  Component Side w15: U1_OI_CH3.3@5709.37,3260 5745,3260 R7_OI_CH3.2@5799.37,3314.37 ; R7_OI_CH3.2@5799.37,3315 R7_OI_CH3.2@5799.37,3314.37 ; R7_OI_CH3.2@5800,3315 R7_OI_CH3.2@5799.37,3314.37 ; TP1_OI_CH3.1@5819.37,3165 TP1_OI_CH3.1@5819.37,3220 ; R20_OI_CH3.1@5909.37,3095 5910,3095.63 R19_OI_CH3.1@5910,3219.37 ; R7_OI_CH3.2@5799.37,3314.37 5799.37,3265 5819.37,3245 TP1_OI_CH3.1@5819.37,3220 ; TP1_OI_CH3.1@5819.37,3220 R19_OI_CH3.1@5909.37,3220 ; R19_OI_CH3.1@5909.37,3220 R19_OI_CH3.1@5910,3219.37 ; R19_OI_CH3.1@5909.37,3220 5910,3220 R19_OI_CH3.1@5910,3219.37
NetR7_OI_CH4_2: R7_OI_CH4.2 R19_OI_CH4.1 R20_OI_CH4.1 TP1_OI_CH4.1 U1_OI_CH4.3 | length 488.5
  Component Side w15: U1_OI_CH4.3@5710,2545 5745.63,2545 R7_OI_CH4.2@5800,2599.37 ; R7_OI_CH4.2@5800,2600 R7_OI_CH4.2@5800,2599.37 ; R7_OI_CH4.2@5800.63,2600 R7_OI_CH4.2@5800,2599.37 ; TP1_OI_CH4.1@5820,2450 TP1_OI_CH4.1@5820,2505 ; R20_OI_CH4.1@5910,2380 5910.63,2380.63 R19_OI_CH4.1@5910.63,2504.37 ; R7_OI_CH4.2@5800,2599.37 5800,2550 5820,2530 TP1_OI_CH4.1@5820,2505 ; TP1_OI_CH4.1@5820,2505 R19_OI_CH4.1@5910,2505 ; R19_OI_CH4.1@5910,2505 R19_OI_CH4.1@5910.63,2504.37 ; R19_OI_CH4.1@5910,2505 R19_OI_CH4.1@5910.63,2505 R19_OI_CH4.1@5910.63,2504.37
NetR8_IO_CH1_1: R8_IO_CH1.1 R9_IO_CH1.3 | length 126
  Component Side w15: R8_IO_CH1.1@5261.54,4475.63 5310.63,4475.63 R9_IO_CH1.3@5365,4530
NetR8_IO_CH2_1: R8_IO_CH2.1 R9_IO_CH2.3 | length 126
  Component Side w15: R8_IO_CH2.1@5261.54,1805.63 5310.63,1805.63 R9_IO_CH2.3@5365,1860
NetR8_OI_CH1_1: R8_OI_CH1.1 R9_OI_CH1.3 | length 105.3
  Component Side w15: R9_OI_CH1.3@2370,6145 2370.63,6144.37 R8_OI_CH1.1@2475,6144.37
NetR8_OI_CH2_1: R8_OI_CH2.1 R9_OI_CH2.3 | length 105.3
  Component Side w15: R9_OI_CH2.3@2370,5430 2370.63,5429.37 R8_OI_CH2.1@2475,5429.37
NetR8_OI_CH3_1: R8_OI_CH3.1 R9_OI_CH3.3 | length 105.3
  Component Side w15: R9_OI_CH3.3@2369.37,3475 2370,3474.37 R8_OI_CH3.1@2474.37,3474.37
NetR8_OI_CH4_1: R8_OI_CH4.1 R9_OI_CH4.3 | length 105.3
  Component Side w15: R9_OI_CH4.3@2370,2760 2370.63,2759.37 R8_OI_CH4.1@2475,2759.37
NetR11_IO_CH1_1: R11_IO_CH1.1 R13_IO_CH1.3 | length 130.1
  Component Side w15: R11_IO_CH1.1@5261.54,4835.63 5272.17,4825 5316.54,4825 R13_IO_CH1.3@5366.54,4875
NetR11_IO_CH2_1: R11_IO_CH2.1 R13_IO_CH2.3 | length 130.1
  Component Side w15: R11_IO_CH2.1@5261.54,2165.63 5272.17,2155 5316.54,2155 R13_IO_CH2.3@5366.54,2205
NetR11_OI_CH1_1: R11_OI_CH1.1 R13_OI_CH1.3 | length 105.3
  Component Side w15: R13_OI_CH1.3@2370,5800 2370.63,5799.37 R11_OI_CH1.1@2475,5799.37
NetR11_OI_CH2_1: R11_OI_CH2.1 R13_OI_CH2.3 | length 105.3
  Component Side w15: R13_OI_CH2.3@2370,5085 2370.63,5084.37 R11_OI_CH2.1@2475,5084.37
NetR11_OI_CH3_1: R11_OI_CH3.1 R13_OI_CH3.3 | length 105.3
  Component Side w15: R13_OI_CH3.3@2369.37,3130 2370,3129.37 R11_OI_CH3.1@2474.37,3129.37
NetR11_OI_CH4_1: R11_OI_CH4.1 R13_OI_CH4.3 | length 105.3
  Component Side w15: R13_OI_CH4.3@2370,2415 2370.63,2414.37 R11_OI_CH4.1@2475,2414.37
NetR14_IO_CH1_1: R14_IO_CH1.1 R16_IO_CH1.3 | length 112.4
  Component Side w15: R14_IO_CH1.1@4861.54,4495 4921.54,4495 4951.54,4525 R16_IO_CH1.3@4961.54,4525
NetR14_IO_CH2_1: R14_IO_CH2.1 R16_IO_CH2.3 | length 112.4
  Component Side w15: R14_IO_CH2.1@4861.54,1825 4921.54,1825 4951.54,1855 R16_IO_CH2.3@4961.54,1855
NetR14_OI_CH1_1: R14_OI_CH1.1 R16_OI_CH1.3 | length 112.4
  Component Side w15: R16_OI_CH1.3@2778.46,6100 2788.46,6100 2818.46,6130 R14_OI_CH1.1@2878.46,6130
NetR14_OI_CH2_1: R14_OI_CH2.1 R16_OI_CH2.3 | length 112.4
  Component Side w15: R16_OI_CH2.3@2778.46,5385 2788.46,5385 2818.46,5415 R14_OI_CH2.1@2878.46,5415
NetR14_OI_CH3_1: R14_OI_CH3.1 R16_OI_CH3.3 | length 112.4
  Component Side w15: R16_OI_CH3.3@2777.83,3430 2787.83,3430 2817.83,3460 R14_OI_CH3.1@2877.83,3460
NetR14_OI_CH4_1: R14_OI_CH4.1 R16_OI_CH4.3 | length 112.4
  Component Side w15: R16_OI_CH4.3@2778.46,2715 2788.46,2715 2818.46,2745 R14_OI_CH4.1@2878.46,2745
NetR17_IO_CH1_1: R17_IO_CH1.1 R18_IO_CH1.3 | length 102.7
  Component Side w15: R17_IO_CH1.1@4861.54,4899.37 4957.17,4899.37 R18_IO_CH1.3@4961.54,4895 ; R18_IO_CH1.3@4960.91,4909.37 R18_IO_CH1.3@4961.54,4910
NetR17_IO_CH2_1: R17_IO_CH2.1 R18_IO_CH2.3 | length 102.7
  Component Side w15: R17_IO_CH2.1@4861.54,2229.37 4957.17,2229.37 R18_IO_CH2.3@4961.54,2225 ; R18_IO_CH2.3@4960.91,2239.37 R18_IO_CH2.3@4961.54,2240
NetR17_OI_CH1_1: R17_OI_CH1.1 R18_OI_CH1.3 | length 102.7
  Component Side w15: R18_OI_CH1.3@2778.46,5715 R18_OI_CH1.3@2779.09,5715.63 ; R18_OI_CH1.3@2778.46,5730 2782.83,5725.63 R17_OI_CH1.1@2878.46,5725.63
NetR17_OI_CH2_1: R17_OI_CH2.1 R18_OI_CH2.3 | length 102.7
  Component Side w15: R18_OI_CH2.3@2778.46,5000 R18_OI_CH2.3@2779.09,5000.63 ; R18_OI_CH2.3@2778.46,5015 2782.83,5010.63 R17_OI_CH2.1@2878.46,5010.63
NetR17_OI_CH3_1: R17_OI_CH3.1 R18_OI_CH3.3 | length 102.7
  Component Side w15: R18_OI_CH3.3@2777.83,3045 R18_OI_CH3.3@2778.46,3045.63 ; R18_OI_CH3.3@2777.83,3060 2782.2,3055.63 R17_OI_CH3.1@2877.83,3055.63
NetR17_OI_CH4_1: R17_OI_CH4.1 R18_OI_CH4.3 | length 102.7
  Component Side w15: R18_OI_CH4.3@2778.46,2330 R18_OI_CH4.3@2779.09,2330.63 ; R18_OI_CH4.3@2778.46,2345 2782.83,2340.63 R17_OI_CH4.1@2878.46,2340.63
PA1: PA.1 R15_OI_CH1.1 | length 1756.7
  Component Side w15: 1286.99,5871.36 1286.99,4593.01 1510,4370 PA.1@1510,4310 ; 1287.82,5872.19 R15_OI_CH1.1@1360.63,5945
PA2: PA.2 R15_OI_CH2.1 | length 1342.5
  Component Side w15: 1315,5170 1315,5184.37 R15_OI_CH2.1@1360.63,5230 ; 1314.99,5181.94 1314.99,4660.01 1595,4380 1595,4260 1545,4210 PA.2@1390,4210
PA3: PA.3 R19_IO_CH1.2 | length 759.3
  Component Side w15: 1750,4310 1750.63,4310.63 R19_IO_CH1.2@1750.63,4740
  Component Side w20: PA.3@1510,4095 1535,4095 1750,4310
PA4: PA.4 R15_OI_CH3.1 | length 1055.8
  Component Side w15: R15_OI_CH3.1@1364.37,3359.37 1364.37,3405.63 1345,3425 1345,3695 1385,3735 1545,3735 1605,3795 1605,3960 1555,4010 PA.4@1380,4010
PA5: PA.5 R15_OI_CH4.1 | length 1419.4
  Component Side w15: 1316.24,3698.76 1316.24,2743.76 1365,2695 R15_OI_CH4.1@1365,2644.37 ; 1316.86,3699.39 1375.47,3758 1468,3758 1510,3800 PA.5@1510,3910
PA6: PA.6 R19_IO_CH2.2 | length 2014.9
  Component Side w15: PA.6@1365,3810 1365,3780.05 1293.24,3708.29 1293.24,2383.35 1391.58,2285 1700,2285 1750.63,2234.37 R19_IO_CH2.2@1750.63,2195
PB1: PB.1 R19_OI_CH1.2 | length 1881.9
  Component Side w15: R19_OI_CH1.2@5989.37,5765 5989.37,5692.51 6448,5233.88 6448,4188 6395,4135 PB.1@6365,4135 PB.1@6365,4145
PB2: PB.2 R19_OI_CH2.2 | length 1532.8
  Component Side w15: 5989.37,4977.51 R19_OI_CH2.2@5989.37,5050 ; 5990,4975 6010,4955 6360,4955 6425,4890 6425,4245 6365,4185 6275.84,4185 6225,4134.16 PB.2@6225,4035
PB3: PB.3 R15_IO_CH1.1 | length 1011.8
  Component Side w15: PB.3@6365,3935 6194.82,3935 6145,3984.82 6145,4100.84 6264.16,4220 6354.39,4220 6395,4260.61 ; R15_IO_CH1.1@6375,4590.63 6375,4550 6395,4530 6395,4260.61 ; 6395,4260 6395,4260.61
PB4: PB.4 R19_OI_CH3.2 | length 768
  Component Side w15: R19_OI_CH3.2@5989.37,3220 5989.37,3324.37 6035,3370 ; 6035,3370.74 6035,3740.87 6129.13,3835 PB.4@6225,3835
PB5: PB.5 R19_OI_CH4.2 | length 1706.8
  Component Side w15: R19_OI_CH4.2@5990,2505 5989.37,2505.63 5989.37,2610.06 6385,3005.69 6385,3323.84 6127.5,3581.34 6127.5,3681.25 6181.25,3735 PB.5@6365,3735
PB6: PB.6 R15_IO_CH2.1 | length 1735
  Component Side w15: PB.6@6225,3635 6225,3585 6435,3375 6435,2071.58 6435,2065.63 R15_IO_CH2.1@6379.37,2010
pads on no net: "U6_Side A power supply and references.1" "U6_Side A power supply and references.3" "U6_Side A power supply and references.5" "U6_Side A power supply and references.7" "U6_Side A power supply and references.8" "U6_Side B power supply and references.1" "U6_Side B power supply and references.3" "U6_Side B power supply and references.5" "U6_Side B power supply and references.7" "U6_Side B power supply and references.8" U2_IO_CH1.1 U2_IO_CH1.5 U2_IO_CH1.8 U2_IO_CH2.1 U2_IO_CH2.5 U2_IO_CH2.8 U2_OI_CH1.1 U2_OI_CH1.5 U2_OI_CH1.8 U2_OI_CH2.1 U2_OI_CH2.5 U2_OI_CH2.8 U2_OI_CH3.1 U2_OI_CH3.5 U2_OI_CH3.8 U2_OI_CH4.1 U2_OI_CH4.5 U2_OI_CH4.8 U3_IO_CH1.7 U3_IO_CH1.8 U3_IO_CH2.7 U3_IO_CH2.8 U3_OI_CH1.7 U3_OI_CH1.8 U3_OI_CH2.7 U3_OI_CH2.8 U3_OI_CH3.7 U3_OI_CH3.8 U3_OI_CH4.7 U3_OI_CH4.8 U4_IO_CH1.1 U4_IO_CH1.5 U4_IO_CH1.8 U4_IO_CH2.1 U4_IO_CH2.5 U4_IO_CH2.8 U4_OI_CH1.1 U4_OI_CH1.5 U4_OI_CH1.8 U4_OI_CH2.1 U4_OI_CH2.5 U4_OI_CH2.8 U4_OI_CH3.1 U4_OI_CH3.5 U4_OI_CH3.8 U4_OI_CH4.1 U4_OI_CH4.5 U4_OI_CH4.8 U5_IO_CH1.1 U5_IO_CH1.5 U5_IO_CH1.8 U5_IO_CH2.1 U5_IO_CH2.5 U5_IO_CH2.8 U5_OI_CH1.1 U5_OI_CH1.5 U5_OI_CH1.8 U5_OI_CH2.1 U5_OI_CH2.5 U5_OI_CH2.8 U5_OI_CH3.1 U5_OI_CH3.5 U5_OI_CH3.8 U5_OI_CH4.1 U5_OI_CH4.5 U5_OI_CH4.8

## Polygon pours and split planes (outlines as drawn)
COMB on Ground "COMB_L04_P002" (solid, remove dead copper, pour order 2): 4000,1010 4000,6960 6730,6960 6730,1010
COMA on Ground "COMA_L04_P000" (solid, remove dead copper, pour order 0): 3750,1010 3750,6960 1010,6960 1010,1010
+15B on V+ "+15B_L02_P006" (solid, remove dead copper, pour order 6): 4000,1010 4000,6960 6730,6960 6730,1010
+15A on V+ "+15A_L02_P004" (solid, remove dead copper, pour order 4): 3750,1010 3750,6960 1010,6960 1010,1010
-15B on V- "-15B_L03_P007" (solid, remove dead copper, pour order 7): 4000,1010 4000,6960 6730,6960 6730,1010
-15A on V- "-15A_L03_P005" (solid, remove dead copper, pour order 5): 3750,1010 3750,6960 1010,6960 1010,1010
COMB on Component Side "COMB_L01_P009" (solid, remove dead copper, pour order 9): 4000,1010 4000,6960 6730,6960 6730,1010
COMA on Component Side "COMA_L01_P008" (solid, remove dead copper, pour order 8): 3750,1010 3750,6960 1010,6960 1010,1010

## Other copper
Ground:
  region net COMA: 1010,1570

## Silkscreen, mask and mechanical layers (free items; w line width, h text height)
Top Overlay:
  lines w6: 1280,2285 3310,2285 ; 1280,3000 3310,3000 ; 1280,3715 3310,3715 ; 1280,4955 3310,4955 ; 1280,5670 3310,5670 ; 1600,4240 3310,4240 ; 4430,2285 6460,2285 ; 4430,3000 6460,3000 ; 4430,3715 6140,3715 ; 4430,4240 6460,4240 ; 4430,4955 6460,4955 ; 4430,5670 6460,5670
  text "2G" at 1815,6330 h40 r270
  text "2B" at 2125,6290 h40
  text "2G" at 2540,6290 h40
  text "10V" at 5485,6260 h40
  text "2V" at 5090,6255 h40
  text "1" at 3840,6195 h80
  text "10G" at 1815,6150 h40 r270
  text "2B" at 1815,5980 h40 r270
  text "10B" at 2125,5945 h40
  text "10G" at 2540,5945 h40
  text "10B" at 1815,5800 h40 r270
  text "2G" at 1815,5615 h40 r270
  text "2B" at 2125,5575 h40
  text "2G" at 2540,5575 h40
  text "10V" at 5480,5545 h40
  text "2V" at 5090,5540 h40
  text "2" at 3830,5485 h80
  text "10G" at 1815,5435 h40 r270
  text "2B" at 1815,5265 h40 r270
  text "10B" at 2125,5230 h40
  text "10G" at 2540,5230 h40
  text "10B" at 1815,5085 h40 r270
  text "10B" at 5875,4930 h40 r270
  text "2B" at 5875,4720 h40 r270
  text "10G" at 5090,4630 h40
  text "10B" at 5505,4630 h40
  text "10G" at 5875,4590 h40 r270
  text "2G" at 5875,4380 h40 r270
  text "2V" at 2575,4330 h40
  text "10V" at 2135,4325 h40
  text "3" at 3835,4325 h80
  text "2G" at 5125,4285 h40
  text "2B" at 5535,4285 h40
  text "1" at 1315,4280 h40
  text "2" at 1540,4185 h40
  text "+15" at 1775,4140 h40
  text "-15" at 5825,4125 h40
  text "1" at 6165,4105 h40
  text "3" at 1310,4080 h40
  text "2" at 6390,4010 h40
  text "4" at 1540,3985 h40
  text "3" at 6160,3905 h40
  text "5" at 1310,3885 h40
  text "4" at 6390,3810 h40
  text "6" at 1540,3785 h40
  text "-15" at 1775,3775 h40
  text "+15" at 5825,3760 h40
  text "5" at 6160,3710 h40
  text "2G" at 1815,3660 h40 r270
  text "2B" at 2125,3620 h40
  text "2G" at 2540,3620 h40
  text "6" at 6390,3610 h40
  text "10V" at 5485,3585 h40
  text "2V" at 5090,3580 h40
  text "4" at 3830,3525 h80
  text "10G" at 1815,3480 h40 r270
  text "2B" at 1815,3310 h40 r270
  text "10B" at 2125,3275 h40
  text "10G" at 2540,3275 h40
  text "10B" at 1815,3130 h40 r270
  text "2G" at 1815,2945 h40 r270
  text "2B" at 2125,2905 h40
  text "2G" at 2540,2905 h40
  text "10V" at 5485,2875 h40
  text "2V" at 5090,2870 h40
  text "5" at 3830,2810 h80
  text "10G" at 1815,2765 h40 r270
  text "2B" at 1815,2595 h40 r270
  text "10B" at 2125,2560 h40
  text "10G" at 2540,2560 h40
  text "10B" at 1815,2415 h40 r270
  text "10B" at 5875,2260 h40 r270
  text "2B" at 5875,2050 h40 r270
  text "10G" at 5090,1960 h40
  text "10B" at 5505,1960 h40
  text "10G" at 5875,1920 h40 r270
  text "2G" at 5875,1710 h40 r270
  text "2V" at 2580,1655 h40
  text "6" at 3835,1655 h80
  text "10V" at 2140,1650 h40
  text "2G" at 5125,1615 h40
  text "2B" at 5535,1615 h40
Bottom Overlay:
  text "E18-029 Isolation Amplifier" at 5985,6480 h50
Top Solder:
  region: 6740,6970 4180,6970 4180,6400 6740,6400
  region: 4420,6400 4180,6400 4180,6222.5 4420,6222.5
  region: 4420,5867.5 4180,5867.5 4180,5509.14 4420,5509.14
  region: 4420,5150 4180,5150 4180,4661.02 4420,4661.02
  region: 4420,4455 4180,4455 4180,3548.86 4420,3548.86
  region: 4420,3197.56 4180,3197.56 4180,2835 4420,2835
  region: 4420,2487.26 4180,2487.26 4180,1991.02 4420,1991.02
  region: 4420,1786.76 4180,1786.76 4180,1570 4420,1570
  region: 6740,1570 4180,1570 4180,1000 6740,1000
  region: 6740,6400 6470,6400 6470,1570 6740,1570
  rectangle: 1000,1570 1270,6400
  rectangle: 1000,1000 3560,1570
  rectangle: 3320,1570 3560,1735
  rectangle: 3320,2085 3560,2580
  rectangle: 3320,2785 3560,3290
  rectangle: 3320,3500 3560,4400
  rectangle: 3320,4760 3560,5260
  rectangle: 3320,5455 3560,5975
  rectangle: 3320,6172.5 3560,6400
  rectangle: 1000,6400 3560,6970
Mechanical 1:
  the board outline again, w2
Mechanical 13:
  lines w2: 1030,1570 3560,1570 ; 1030,6400 3560,6400 ; 1270,1265 1270,6695 ; 3320,1265 3320,6695 ; 4180,1570 6710,1570 ; 4180,6400 6710,6400 ; 4420,1265 4420,6695 ; 6470,1265 6470,6695 ; 1030,1030 1030,6940 3560,6940 3560,1030 1030,1030 ; 4180,1030 6710,1030 6710,6940 4180,6940 4180,1030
